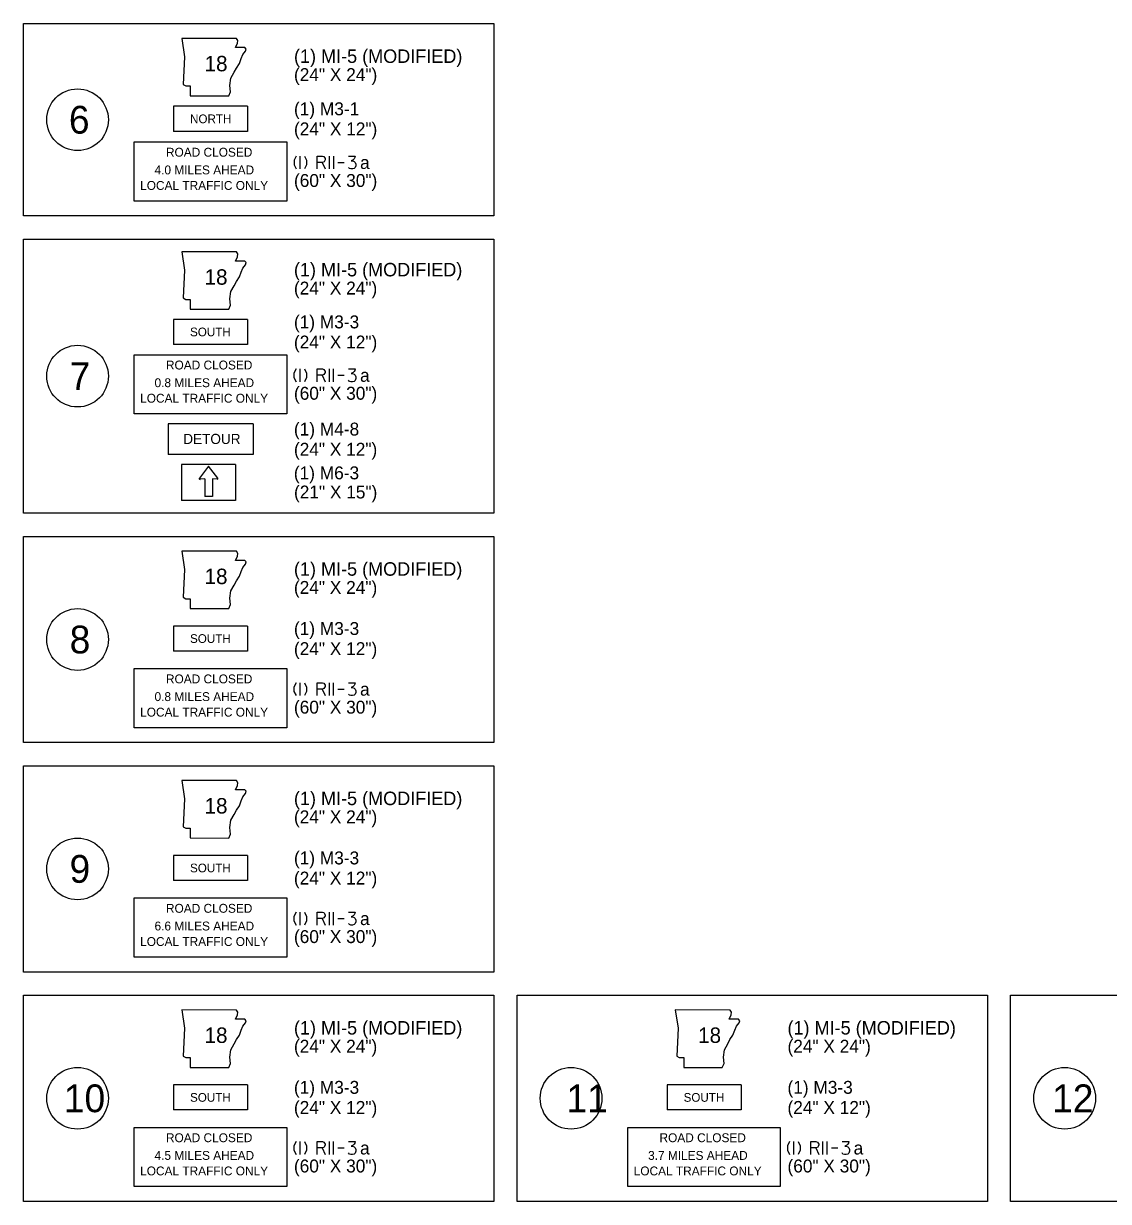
# Model space of a CAD drawing. Extents: x -31818 to 1228740, y -23925 to 152440.
# Drawn here: x -31809.4 to -31762.5, y -23923.3 to -23872.4 of the extents above; entities that cross this region are included whole.
import ezdxf

# ---------------------------------------------------------------- set-up
doc = ezdxf.new("R2010")
doc.units = 0
for name, color, linetype in [('21', 7, 'Continuous'), ('3', 7, 'Continuous'), ('59', 7, 'Continuous'), ('8', 7, 'Continuous'), ('Level 1', 7, 'Continuous'), ('Level 3', 7, 'Continuous'), ('Level 8', 7, 'Continuous'), ('shading', 7, 'Continuous')]:
    doc.layers.add(name, color=color, linetype=linetype)

msp = doc.modelspace()

# ---------------------------------------------------------------- linework, layer by layer
at = {"layer": '21'}
for points in [[(-31802.563, -23873.04), (-31802.445, -23873.832), (-31802.499, -23875.033), (-31802.394, -23875.099), (-31802.196, -23875.099), (-31802.196, -23875.522), (-31800.534, -23875.523), (-31800.454, -23875.352), (-31800.481, -23875.075), (-31800.441, -23874.758), (-31800.295, -23874.507), (-31800.203, -23874.323), (-31800.07, -23874.125), (-31799.991, -23873.914), (-31799.925, -23873.742), (-31799.806, -23873.597), (-31799.779, -23873.505), (-31799.832, -23873.439), (-31800.242, -23873.439), (-31800.149, -23873.254), (-31800.135, -23873.135), (-31800.19, -23873.044)], [(-31802.563, -23882.266), (-31802.445, -23883.058), (-31802.499, -23884.259), (-31802.394, -23884.325), (-31802.196, -23884.325), (-31802.196, -23884.748), (-31800.534, -23884.749), (-31800.454, -23884.577), (-31800.481, -23884.3), (-31800.441, -23883.984), (-31800.295, -23883.733), (-31800.203, -23883.548), (-31800.07, -23883.351), (-31799.991, -23883.14), (-31799.925, -23882.968), (-31799.806, -23882.823), (-31799.779, -23882.731), (-31799.832, -23882.665), (-31800.242, -23882.664), (-31800.149, -23882.48), (-31800.135, -23882.361), (-31800.19, -23882.27)], [(-31802.563, -23895.206), (-31802.445, -23895.998), (-31802.499, -23897.199), (-31802.394, -23897.265), (-31802.196, -23897.265), (-31802.196, -23897.688), (-31800.534, -23897.689), (-31800.454, -23897.518), (-31800.481, -23897.24), (-31800.441, -23896.924), (-31800.295, -23896.673), (-31800.203, -23896.488), (-31800.07, -23896.291), (-31799.991, -23896.08), (-31799.925, -23895.908), (-31799.806, -23895.763), (-31799.779, -23895.671), (-31799.832, -23895.605), (-31800.242, -23895.604), (-31800.149, -23895.42), (-31800.135, -23895.301), (-31800.19, -23895.21)], [(-31802.563, -23905.122), (-31802.445, -23905.914), (-31802.499, -23907.115), (-31802.394, -23907.181), (-31802.196, -23907.181), (-31802.196, -23907.604), (-31800.534, -23907.605), (-31800.454, -23907.434), (-31800.481, -23907.156), (-31800.441, -23906.84), (-31800.295, -23906.589), (-31800.203, -23906.405), (-31800.07, -23906.207), (-31799.991, -23905.996), (-31799.925, -23905.824), (-31799.806, -23905.679), (-31799.779, -23905.587), (-31799.832, -23905.521), (-31800.242, -23905.521), (-31800.149, -23905.336), (-31800.135, -23905.217), (-31800.19, -23905.126)], [(-31802.563, -23915.038), (-31802.445, -23915.83), (-31802.499, -23917.031), (-31802.394, -23917.097), (-31802.196, -23917.097), (-31802.196, -23917.52), (-31800.534, -23917.521), (-31800.454, -23917.35), (-31800.481, -23917.072), (-31800.441, -23916.756), (-31800.295, -23916.505), (-31800.203, -23916.321), (-31800.07, -23916.123), (-31799.991, -23915.912), (-31799.925, -23915.74), (-31799.806, -23915.595), (-31799.779, -23915.503), (-31799.832, -23915.437), (-31800.242, -23915.437), (-31800.149, -23915.252), (-31800.135, -23915.133), (-31800.19, -23915.042)], [(-31781.228, -23915.038), (-31781.11, -23915.83), (-31781.164, -23917.031), (-31781.059, -23917.097), (-31780.861, -23917.097), (-31780.861, -23917.52), (-31779.199, -23917.521), (-31779.119, -23917.35), (-31779.146, -23917.072), (-31779.106, -23916.756), (-31778.96, -23916.505), (-31778.867, -23916.321), (-31778.735, -23916.123), (-31778.656, -23915.912), (-31778.59, -23915.74), (-31778.471, -23915.595), (-31778.444, -23915.503), (-31778.497, -23915.437), (-31778.906, -23915.437), (-31778.814, -23915.252), (-31778.8, -23915.133), (-31778.855, -23915.042)]]:
    msp.add_lwpolyline(points, close=True, dxfattribs=at)
at = {"layer": '3'}
for centre, start, end in [((-31801.777, -23892.068), 142.3888, 274.5739), ((-31801.031, -23892.068), 265.4261, 37.6147)]:
    msp.add_arc(centre, 0.0334, start, end, dxfattribs=at)
at = {"layer": '59'}
for p, q in [((-31799.719, -23875.975), (-31802.92, -23875.975)), ((-31802.92, -23875.975), (-31802.92, -23877.062)), ((-31799.719, -23875.975), (-31799.719, -23877.062)), ((-31799.719, -23877.062), (-31802.92, -23877.062)), ((-31799.719, -23885.187), (-31802.92, -23885.187)), ((-31802.92, -23885.187), (-31802.92, -23886.274)), ((-31799.719, -23885.187), (-31799.719, -23886.274)), ((-31799.719, -23886.274), (-31802.92, -23886.274)), ((-31799.482, -23889.707), (-31803.157, -23889.707)), ((-31803.157, -23889.707), (-31803.157, -23891.024)), ((-31799.482, -23889.707), (-31799.482, -23891.024)), ((-31799.482, -23891.024), (-31803.157, -23891.024)), ((-31800.234, -23891.457), (-31802.574, -23891.457)), ((-31802.574, -23891.457), (-31802.574, -23893.015)), ((-31801.404, -23891.529), (-31801.803, -23892.047)), ((-31801.004, -23892.048), (-31801.404, -23891.529)), ((-31800.234, -23891.457), (-31800.234, -23893.015)), ((-31801.571, -23892.085), (-31801.774, -23892.101)), ((-31801.571, -23892.085), (-31801.571, -23892.844)), ((-31801.033, -23892.101), (-31801.237, -23892.085)), ((-31800.234, -23893.015), (-31802.574, -23893.015)), ((-31799.719, -23898.441), (-31802.92, -23898.441)), ((-31802.92, -23898.441), (-31802.92, -23899.528)), ((-31799.719, -23898.441), (-31799.719, -23899.528)), ((-31799.719, -23899.528), (-31802.92, -23899.528)), ((-31799.719, -23908.357), (-31802.92, -23908.357)), ((-31802.92, -23908.357), (-31802.92, -23909.444)), ((-31799.719, -23908.357), (-31799.719, -23909.444)), ((-31799.719, -23909.444), (-31802.92, -23909.444)), ((-31799.719, -23918.273), (-31802.92, -23918.273)), ((-31802.92, -23918.273), (-31802.92, -23919.36)), ((-31799.719, -23918.273), (-31799.719, -23919.36)), ((-31778.384, -23918.273), (-31781.585, -23918.273)), ((-31781.585, -23918.273), (-31781.585, -23919.36)), ((-31778.384, -23918.273), (-31778.384, -23919.36)), ((-31799.719, -23919.36), (-31802.92, -23919.36)), ((-31778.384, -23919.36), (-31781.585, -23919.36))]:
    msp.add_line(p, q, dxfattribs=at)
msp.add_lwpolyline([(-31801.237, -23892.085), (-31801.237, -23892.844), (-31801.571, -23892.844)], dxfattribs=at)
at = {"layer": '8'}
for points in [[(-31809.402, -23872.4), (-31789.067, -23872.4), (-31789.067, -23880.716), (-31809.402, -23880.716)], [(-31809.402, -23881.716), (-31789.067, -23881.716), (-31789.067, -23893.566), (-31809.402, -23893.566)], [(-31809.402, -23894.566), (-31789.067, -23894.566), (-31789.067, -23903.482), (-31809.402, -23903.482)], [(-31809.402, -23904.482), (-31789.067, -23904.482), (-31789.067, -23913.398), (-31809.402, -23913.398)], [(-31809.402, -23914.398), (-31789.067, -23914.398), (-31789.067, -23923.314), (-31809.402, -23923.314)], [(-31788.067, -23914.398), (-31767.732, -23914.398), (-31767.732, -23923.314), (-31788.067, -23923.314)], [(-31766.732, -23914.398), (-31746.397, -23914.398), (-31746.397, -23923.314), (-31766.732, -23923.314)]]:
    msp.add_lwpolyline(points, close=True, dxfattribs=at)
at = {"layer": 'Level 1'}
for points in [[(-31804.615, -23877.515), (-31798.024, -23877.515), (-31798.024, -23880.075), (-31804.615, -23880.075)], [(-31804.615, -23886.713), (-31798.024, -23886.713), (-31798.024, -23889.273), (-31804.615, -23889.273)], [(-31804.615, -23900.281), (-31798.024, -23900.281), (-31798.024, -23902.841), (-31804.615, -23902.841)], [(-31804.615, -23910.197), (-31798.024, -23910.197), (-31798.024, -23912.757), (-31804.615, -23912.757)], [(-31804.615, -23920.113), (-31798.024, -23920.113), (-31798.024, -23922.673), (-31804.615, -23922.673)], [(-31783.28, -23920.113), (-31776.689, -23920.113), (-31776.689, -23922.673), (-31783.28, -23922.673)]]:
    msp.add_lwpolyline(points, close=True, dxfattribs=at)
at = {"layer": 'Level 8'}
for p, q in [((-31797.438, -23878.686), (-31797.438, -23878.127)), ((-31796.181, -23878.686), (-31796.181, -23878.127)), ((-31795.996, -23878.686), (-31795.996, -23878.127)), ((-31796.489, -23878.4), (-31796.361, -23878.686)), ((-31795.812, -23878.404), (-31795.539, -23878.404)), ((-31797.44, -23887.884), (-31797.44, -23887.325)), ((-31796.49, -23887.598), (-31796.363, -23887.884)), ((-31796.182, -23887.884), (-31796.182, -23887.325)), ((-31795.998, -23887.884), (-31795.998, -23887.325)), ((-31795.813, -23887.602), (-31795.541, -23887.602)), ((-31797.44, -23901.452), (-31797.44, -23900.893)), ((-31796.182, -23901.452), (-31796.182, -23900.893)), ((-31795.998, -23901.452), (-31795.998, -23900.893)), ((-31796.49, -23901.166), (-31796.363, -23901.452)), ((-31795.813, -23901.17), (-31795.541, -23901.17)), ((-31797.44, -23911.368), (-31797.44, -23910.809)), ((-31796.49, -23911.082), (-31796.363, -23911.368)), ((-31796.182, -23911.368), (-31796.182, -23910.809)), ((-31795.998, -23911.368), (-31795.998, -23910.809)), ((-31795.813, -23911.086), (-31795.541, -23911.086)), ((-31797.44, -23921.284), (-31797.44, -23920.725)), ((-31796.182, -23921.284), (-31796.182, -23920.725)), ((-31795.998, -23921.284), (-31795.998, -23920.725)), ((-31776.105, -23921.284), (-31776.105, -23920.725)), ((-31774.847, -23921.284), (-31774.847, -23920.725)), ((-31774.663, -23921.284), (-31774.663, -23920.725)), ((-31796.49, -23920.998), (-31796.363, -23921.284)), ((-31795.813, -23921.002), (-31795.541, -23921.002)), ((-31775.155, -23920.998), (-31775.028, -23921.284)), ((-31774.478, -23921.002), (-31774.206, -23921.002))]:
    msp.add_line(p, q, dxfattribs=at)
for points in [[(-31797.623, -23878.127), (-31797.711, -23878.312), (-31797.711, -23878.501), (-31797.623, -23878.686)], [(-31797.254, -23878.127), (-31797.166, -23878.312), (-31797.166, -23878.501), (-31797.254, -23878.686)], [(-31796.709, -23878.686), (-31796.709, -23878.127), (-31796.484, -23878.127), (-31796.418, -23878.149), (-31796.361, -23878.237), (-31796.361, -23878.29), (-31796.414, -23878.378), (-31796.484, -23878.4), (-31796.709, -23878.4)], [(-31795.355, -23878.127), (-31795.06, -23878.127), (-31795.078, -23878.193), (-31795.108, -23878.242), (-31795.152, -23878.286), (-31795.24, -23878.33), (-31795.174, -23878.33), (-31795.104, -23878.36), (-31795.06, -23878.404), (-31795.038, -23878.475), (-31795.038, -23878.55), (-31795.06, -23878.624), (-31795.108, -23878.668), (-31795.174, -23878.686), (-31795.249, -23878.686), (-31795.315, -23878.668), (-31795.355, -23878.62)], [(-31797.624, -23887.325), (-31797.712, -23887.51), (-31797.712, -23887.699), (-31797.624, -23887.884)], [(-31797.255, -23887.325), (-31797.167, -23887.51), (-31797.167, -23887.699), (-31797.255, -23887.884)], [(-31796.71, -23887.884), (-31796.71, -23887.325), (-31796.486, -23887.325), (-31796.42, -23887.347), (-31796.363, -23887.435), (-31796.363, -23887.488), (-31796.415, -23887.576), (-31796.486, -23887.598), (-31796.71, -23887.598)], [(-31795.356, -23887.325), (-31795.061, -23887.325), (-31795.079, -23887.391), (-31795.11, -23887.44), (-31795.154, -23887.484), (-31795.242, -23887.527), (-31795.176, -23887.527), (-31795.105, -23887.558), (-31795.061, -23887.602), (-31795.039, -23887.673), (-31795.039, -23887.747), (-31795.061, -23887.822), (-31795.11, -23887.866), (-31795.176, -23887.884), (-31795.25, -23887.884), (-31795.316, -23887.866), (-31795.356, -23887.818)], [(-31797.624, -23900.893), (-31797.712, -23901.078), (-31797.712, -23901.267), (-31797.624, -23901.452)], [(-31797.255, -23900.893), (-31797.167, -23901.078), (-31797.167, -23901.267), (-31797.255, -23901.452)], [(-31796.71, -23901.452), (-31796.71, -23900.893), (-31796.486, -23900.893), (-31796.42, -23900.915), (-31796.363, -23901.003), (-31796.363, -23901.056), (-31796.415, -23901.144), (-31796.486, -23901.166), (-31796.71, -23901.166)], [(-31795.356, -23900.893), (-31795.061, -23900.893), (-31795.079, -23900.959), (-31795.11, -23901.008), (-31795.154, -23901.052), (-31795.242, -23901.096), (-31795.176, -23901.096), (-31795.105, -23901.126), (-31795.061, -23901.17), (-31795.039, -23901.241), (-31795.039, -23901.315), (-31795.061, -23901.39), (-31795.11, -23901.434), (-31795.176, -23901.452), (-31795.25, -23901.452), (-31795.316, -23901.434), (-31795.356, -23901.386)], [(-31797.624, -23910.809), (-31797.712, -23910.994), (-31797.712, -23911.183), (-31797.624, -23911.368)], [(-31797.255, -23910.809), (-31797.167, -23910.994), (-31797.167, -23911.183), (-31797.255, -23911.368)], [(-31796.71, -23911.368), (-31796.71, -23910.809), (-31796.486, -23910.809), (-31796.42, -23910.831), (-31796.363, -23910.919), (-31796.363, -23910.972), (-31796.415, -23911.06), (-31796.486, -23911.082), (-31796.71, -23911.082)], [(-31795.356, -23910.809), (-31795.061, -23910.809), (-31795.079, -23910.875), (-31795.11, -23910.924), (-31795.154, -23910.968), (-31795.242, -23911.012), (-31795.176, -23911.012), (-31795.105, -23911.042), (-31795.061, -23911.086), (-31795.039, -23911.157), (-31795.039, -23911.231), (-31795.061, -23911.306), (-31795.11, -23911.35), (-31795.176, -23911.368), (-31795.25, -23911.368), (-31795.316, -23911.35), (-31795.356, -23911.302)], [(-31797.624, -23920.725), (-31797.712, -23920.91), (-31797.712, -23921.099), (-31797.624, -23921.284)], [(-31797.255, -23920.725), (-31797.167, -23920.91), (-31797.167, -23921.099), (-31797.255, -23921.284)], [(-31796.71, -23921.284), (-31796.71, -23920.725), (-31796.486, -23920.725), (-31796.42, -23920.747), (-31796.363, -23920.835), (-31796.363, -23920.888), (-31796.415, -23920.976), (-31796.486, -23920.998), (-31796.71, -23920.998)], [(-31795.356, -23920.725), (-31795.061, -23920.725), (-31795.079, -23920.791), (-31795.11, -23920.84), (-31795.154, -23920.884), (-31795.242, -23920.928), (-31795.176, -23920.928), (-31795.105, -23920.958), (-31795.061, -23921.002), (-31795.039, -23921.073), (-31795.039, -23921.147), (-31795.061, -23921.222), (-31795.11, -23921.266), (-31795.176, -23921.284), (-31795.25, -23921.284), (-31795.316, -23921.266), (-31795.356, -23921.218)], [(-31776.289, -23920.725), (-31776.377, -23920.91), (-31776.377, -23921.099), (-31776.289, -23921.284)], [(-31775.92, -23920.725), (-31775.832, -23920.91), (-31775.832, -23921.099), (-31775.92, -23921.284)], [(-31775.375, -23921.284), (-31775.375, -23920.725), (-31775.151, -23920.725), (-31775.085, -23920.747), (-31775.028, -23920.835), (-31775.028, -23920.888), (-31775.08, -23920.976), (-31775.151, -23920.998), (-31775.375, -23920.998)], [(-31774.021, -23920.725), (-31773.726, -23920.725), (-31773.744, -23920.791), (-31773.775, -23920.84), (-31773.819, -23920.884), (-31773.907, -23920.928), (-31773.841, -23920.928), (-31773.77, -23920.958), (-31773.726, -23921.002), (-31773.704, -23921.073), (-31773.704, -23921.147), (-31773.726, -23921.222), (-31773.775, -23921.266), (-31773.841, -23921.284), (-31773.915, -23921.284), (-31773.981, -23921.266), (-31774.021, -23921.218)]]:
    msp.add_lwpolyline(points, dxfattribs=at)
for centre in [(-31807.068, -23876.558), (-31807.068, -23887.641), (-31807.068, -23899.024), (-31807.068, -23908.94), (-31807.068, -23918.856), (-31785.733, -23918.856), (-31764.398, -23918.856)]:
    msp.add_circle(centre, 1.333, dxfattribs=at)
at = {"layer": 'shading'}
for centre in [(-31807.068, -23876.558), (-31807.068, -23887.641), (-31807.068, -23899.024), (-31807.068, -23908.94), (-31807.068, -23918.856), (-31785.733, -23918.856), (-31764.398, -23918.856)]:
    msp.add_circle(centre, 1.333, dxfattribs=at)

# ---------------------------------------------------------------- texts
at = {"layer": '3'}
for s, height, p in [('NORTH', 0.3759, (-31802.205, -23876.707)), ('SOUTH', 0.3759, (-31802.205, -23885.918)), ('DETOUR', 0.4386, (-31802.499, -23890.574)), ('SOUTH', 0.3759, (-31802.205, -23899.172)), ('SOUTH', 0.3759, (-31802.205, -23909.088)), ('SOUTH', 0.3759, (-31802.205, -23919.005)), ('SOUTH', 0.3759, (-31780.87, -23919.005))]:
    msp.add_text(s, height=height, rotation=360, dxfattribs=at).set_placement(p)
at = {"layer": '8'}
for p in [(-31801.577, -23874.464), (-31801.577, -23883.689), (-31801.577, -23896.63), (-31801.577, -23906.546), (-31801.577, -23916.462), (-31780.242, -23916.462)]:
    msp.add_text('18', height=0.667, dxfattribs=at).set_placement(p)
at = {"layer": 'Level 1'}
for s, p in [('4.0 MILES AHEAD', (-31803.74, -23878.919)), ('0.8 MILES AHEAD', (-31803.74, -23888.117)), ('0.8 MILES AHEAD', (-31803.74, -23901.685)), ('6.6 MILES AHEAD', (-31803.74, -23911.601)), ('4.5 MILES AHEAD', (-31803.74, -23921.517)), ('3.7 MILES AHEAD', (-31782.405, -23921.517))]:
    msp.add_text(s, height=0.38362, dxfattribs=at).set_placement(p)
at = {"layer": 'Level 3'}
for s, p in [('ROAD CLOSED', (-31803.246, -23878.154)), ('LOCAL TRAFFIC ONLY', (-31804.362, -23879.59)), ('ROAD CLOSED', (-31803.246, -23887.352)), ('LOCAL TRAFFIC ONLY', (-31804.362, -23888.788)), ('ROAD CLOSED', (-31803.246, -23900.92)), ('LOCAL TRAFFIC ONLY', (-31804.362, -23902.356)), ('ROAD CLOSED', (-31803.246, -23910.836)), ('LOCAL TRAFFIC ONLY', (-31804.362, -23912.272)), ('ROAD CLOSED', (-31803.246, -23920.752)), ('ROAD CLOSED', (-31781.911, -23920.752)), ('LOCAL TRAFFIC ONLY', (-31804.362, -23922.188)), ('LOCAL TRAFFIC ONLY', (-31783.027, -23922.188))]:
    msp.add_text(s, height=0.38363, dxfattribs=at).set_placement(p)
at = {"layer": 'Level 8'}
for s, height, rotation, p in [('(1) MI-5 (MODIFIED)', 0.58333, 360, (-31797.712, -23874.102)), ('(24" X 24")', 0.55832, 0, (-31797.712, -23874.887)), ('(1) M3-1', 0.5583, 0, (-31797.712, -23876.363)), ('(24" X 12")', 0.55832, 0, (-31797.712, -23877.233)), ('(1) MI-5 (MODIFIED)', 0.58333, 360, (-31797.714, -23883.328)), ('(24" X 24")', 0.55832, 0, (-31797.714, -23884.113)), ('(1) M3-3', 0.5583, 0, (-31797.714, -23885.575)), ('(24" X 12")', 0.55832, 0, (-31797.714, -23886.445)), ('(1) M4-8', 0.5583, 360, (-31797.714, -23890.208)), ('(24" X 12")', 0.55832, 360, (-31797.714, -23891.081)), ('(1) M6-3', 0.5583, 360, (-31797.717, -23892.101)), ('(21" X 15")', 0.55832, 360, (-31797.711, -23892.929)), ('(1) MI-5 (MODIFIED)', 0.58333, 360, (-31797.714, -23896.268)), ('(24" X 24")', 0.55832, 0, (-31797.714, -23897.053)), ('(1) M3-3', 0.5583, 0, (-31797.714, -23898.829)), ('(24" X 12")', 0.55832, 0, (-31797.714, -23899.699)), ('(1) MI-5 (MODIFIED)', 0.58333, 360, (-31797.714, -23906.184)), ('(24" X 24")', 0.55832, 0, (-31797.714, -23906.969)), ('(1) M3-3', 0.5583, 0, (-31797.714, -23908.745)), ('(24" X 12")', 0.55832, 0, (-31797.714, -23909.615)), ('(1) MI-5 (MODIFIED)', 0.58333, 360, (-31797.714, -23916.1)), ('(1) MI-5 (MODIFIED)', 0.58333, 360, (-31776.379, -23916.1)), ('(24" X 24")', 0.55832, 0, (-31797.714, -23916.885)), ('(24" X 24")', 0.55832, 0, (-31776.379, -23916.885)), ('(1) M3-3', 0.5583, 0, (-31797.714, -23918.661)), ('(1) M3-3', 0.5583, 0, (-31776.379, -23918.661)), ('(24" X 12")', 0.55832, 0, (-31797.714, -23919.531)), ('(24" X 12")', 0.55832, 0, (-31776.379, -23919.531))]:
    msp.add_text(s, height=height, rotation=rotation, dxfattribs=at).set_placement(p)
for s, height, p in [('6', 1.2, (-31807.442, -23877.158)), ('a', 0.558, (-31794.855, -23878.686)), ('(60" X 30")', 0.55829, (-31797.712, -23879.463)), ('7', 1.2, (-31807.409, -23888.241)), ('a', 0.558, (-31794.856, -23887.884)), ('(60" X 30")', 0.55829, (-31797.714, -23888.66)), ('8', 1.2, (-31807.409, -23899.624)), ('a', 0.558, (-31794.856, -23901.452)), ('(60" X 30")', 0.55829, (-31797.714, -23902.228)), ('9', 1.2, (-31807.413, -23909.54)), ('a', 0.558, (-31794.856, -23911.368)), ('(60" X 30")', 0.55829, (-31797.714, -23912.145)), ('10', 1.2, (-31807.659, -23919.456)), ('11', 1.2, (-31785.932, -23919.456)), ('12', 1.2, (-31764.937, -23919.456)), ('a', 0.558, (-31794.856, -23921.284)), ('a', 0.558, (-31773.521, -23921.284)), ('(60" X 30")', 0.55829, (-31797.714, -23922.061)), ('(60" X 30")', 0.55829, (-31776.379, -23922.061))]:
    msp.add_text(s, height=height, dxfattribs=at).set_placement(p)

doc.saveas('drawing.dxf')
